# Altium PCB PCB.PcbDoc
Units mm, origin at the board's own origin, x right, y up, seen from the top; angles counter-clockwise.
Board outline 66 x 71.8 mm, 4 copper layers (TOP, GND, PWR, BOTTOM), stack 1.586 mm thick; 30 components, 60 nets, 199 pads, 109 vias.
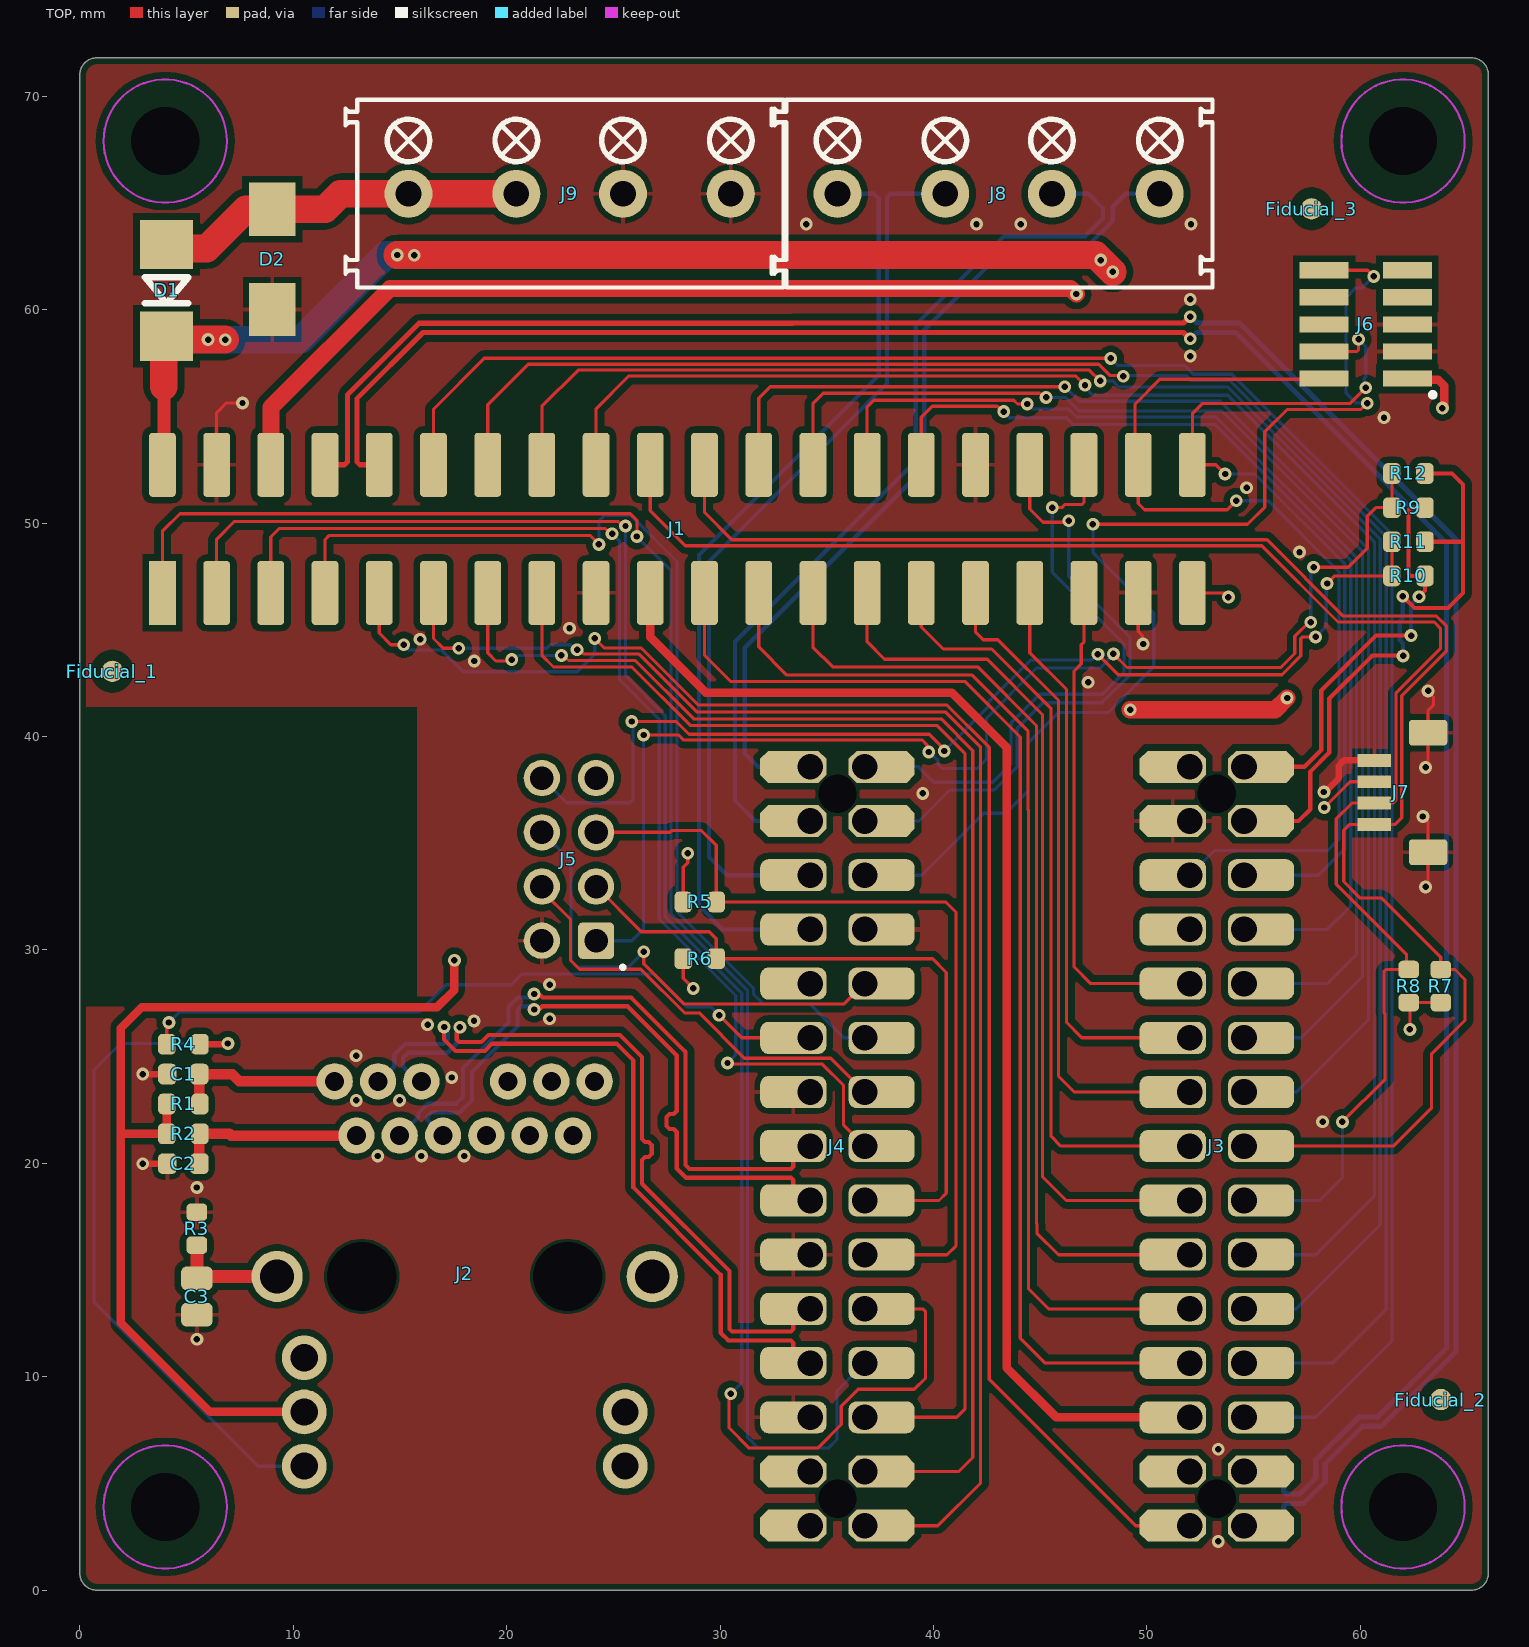
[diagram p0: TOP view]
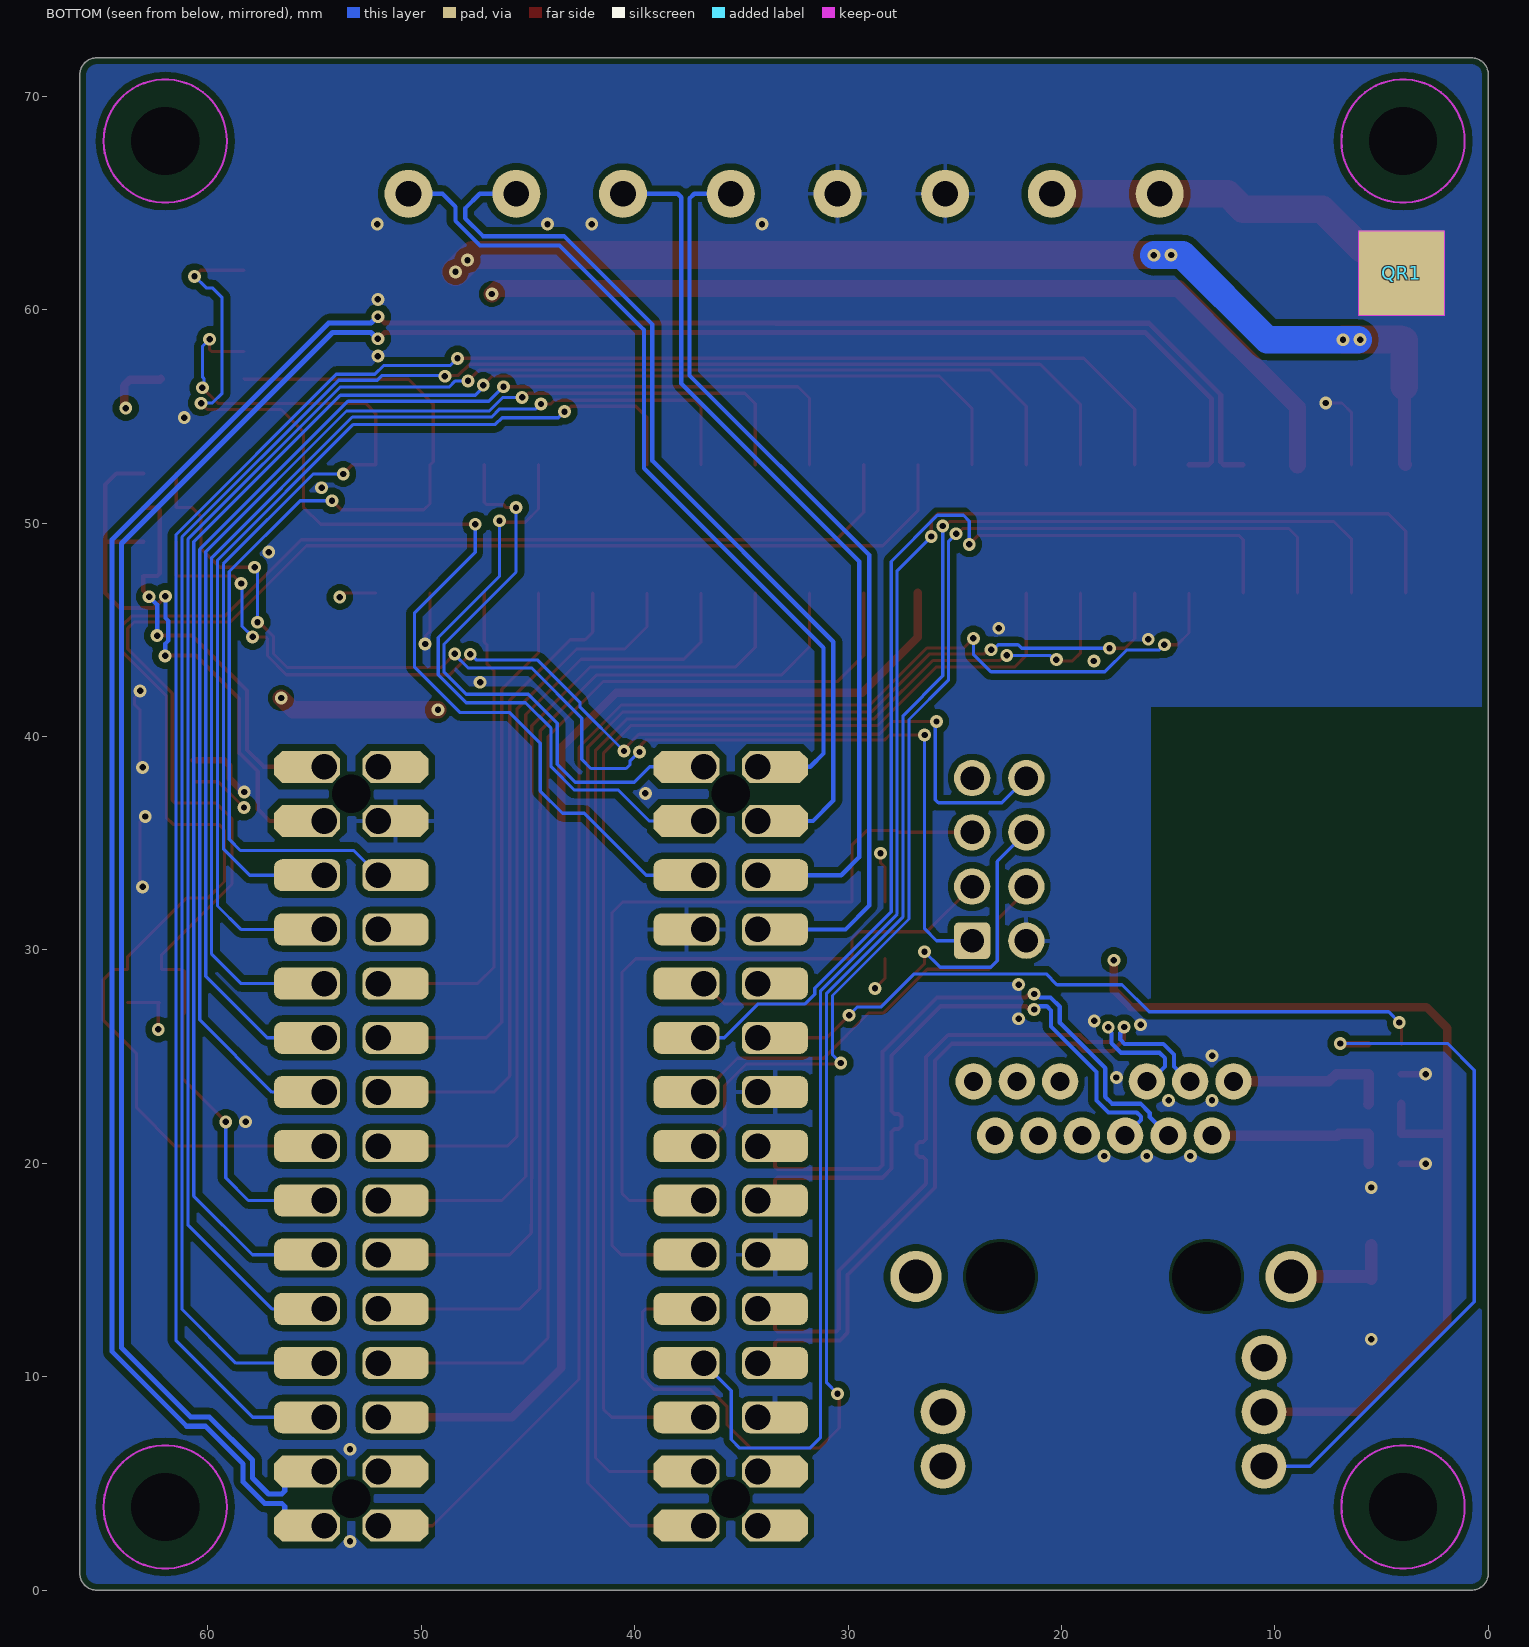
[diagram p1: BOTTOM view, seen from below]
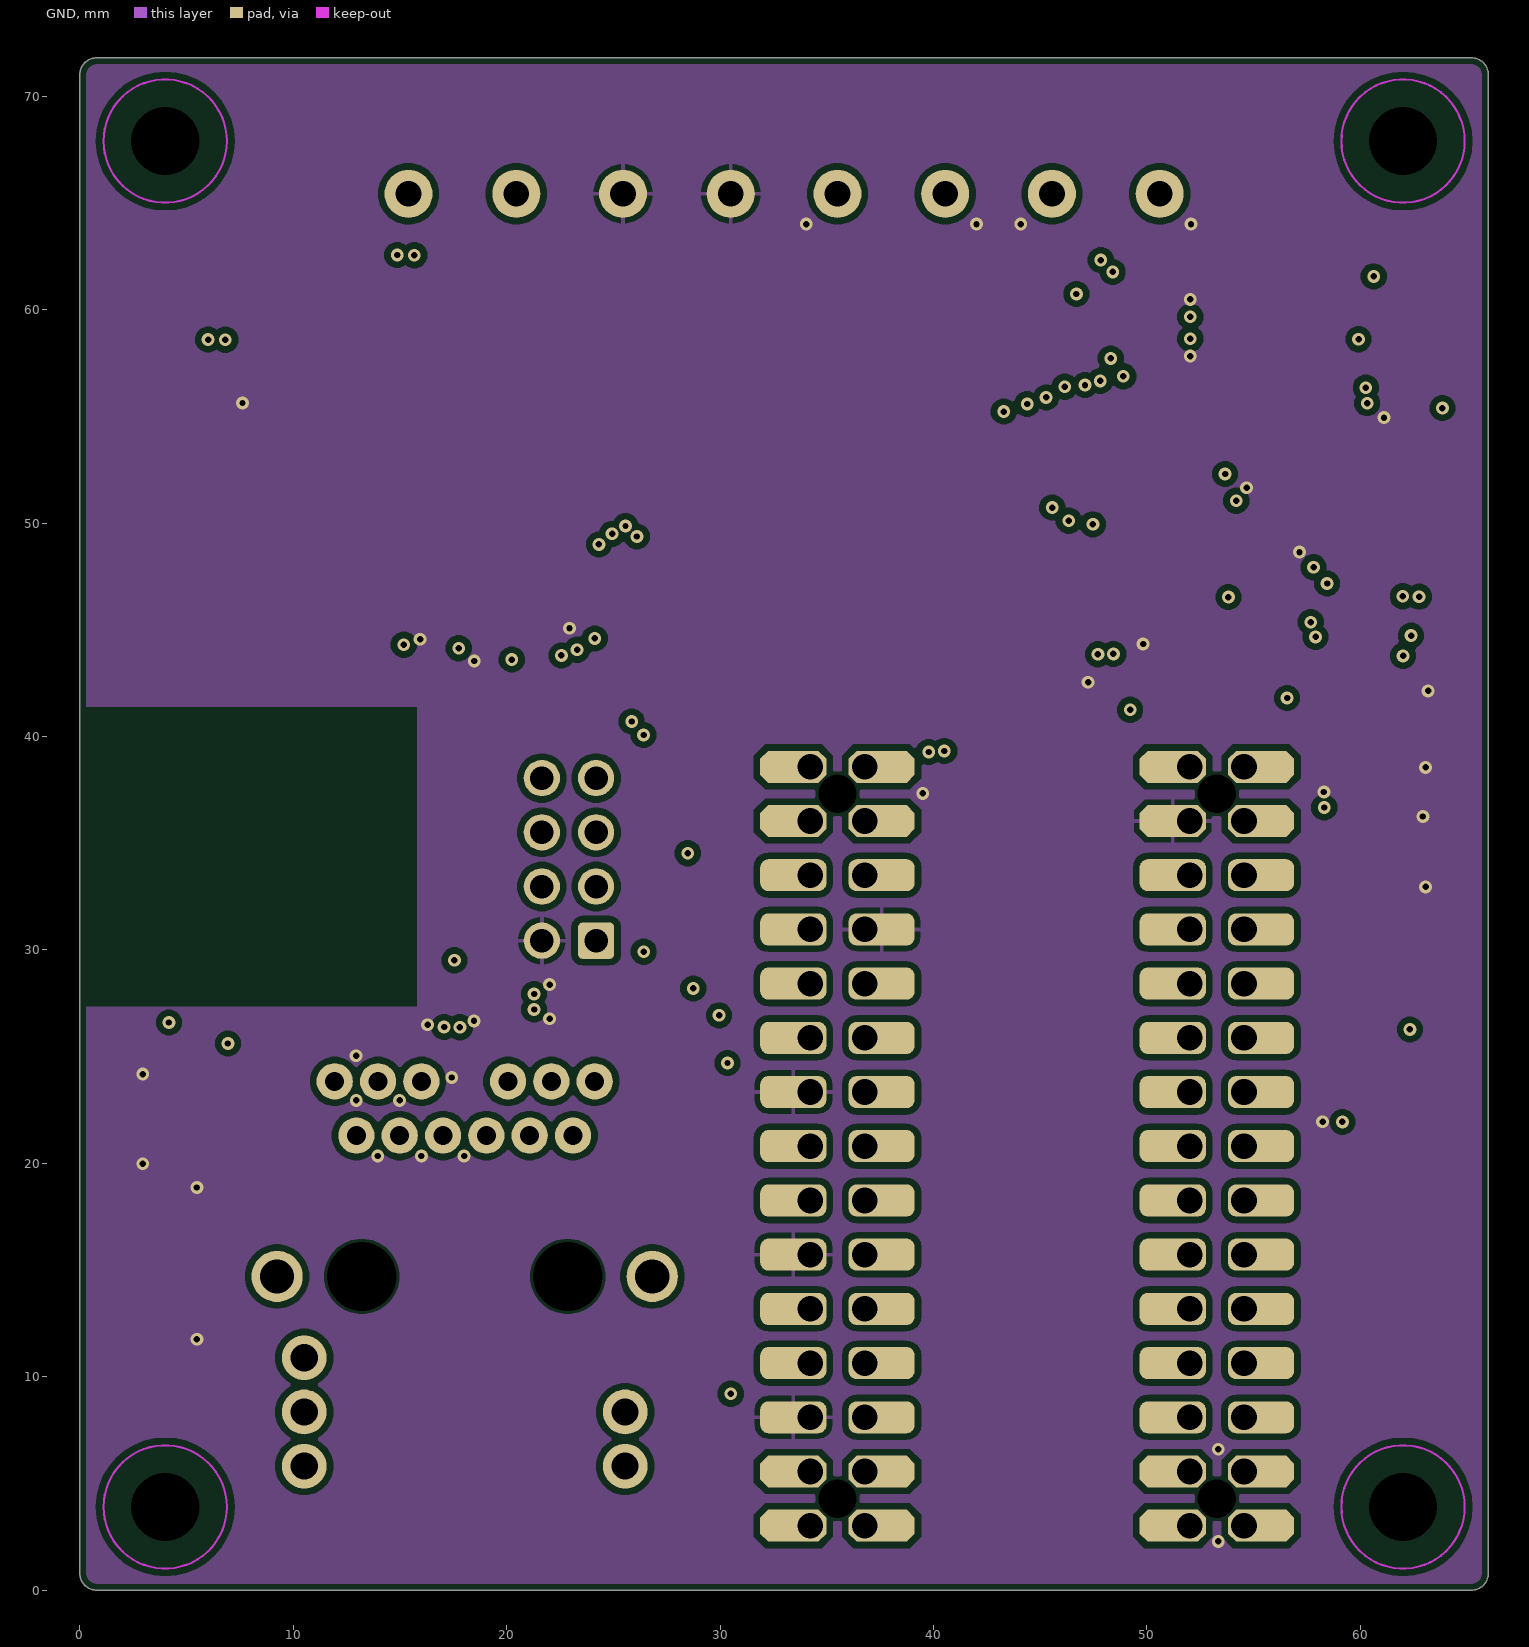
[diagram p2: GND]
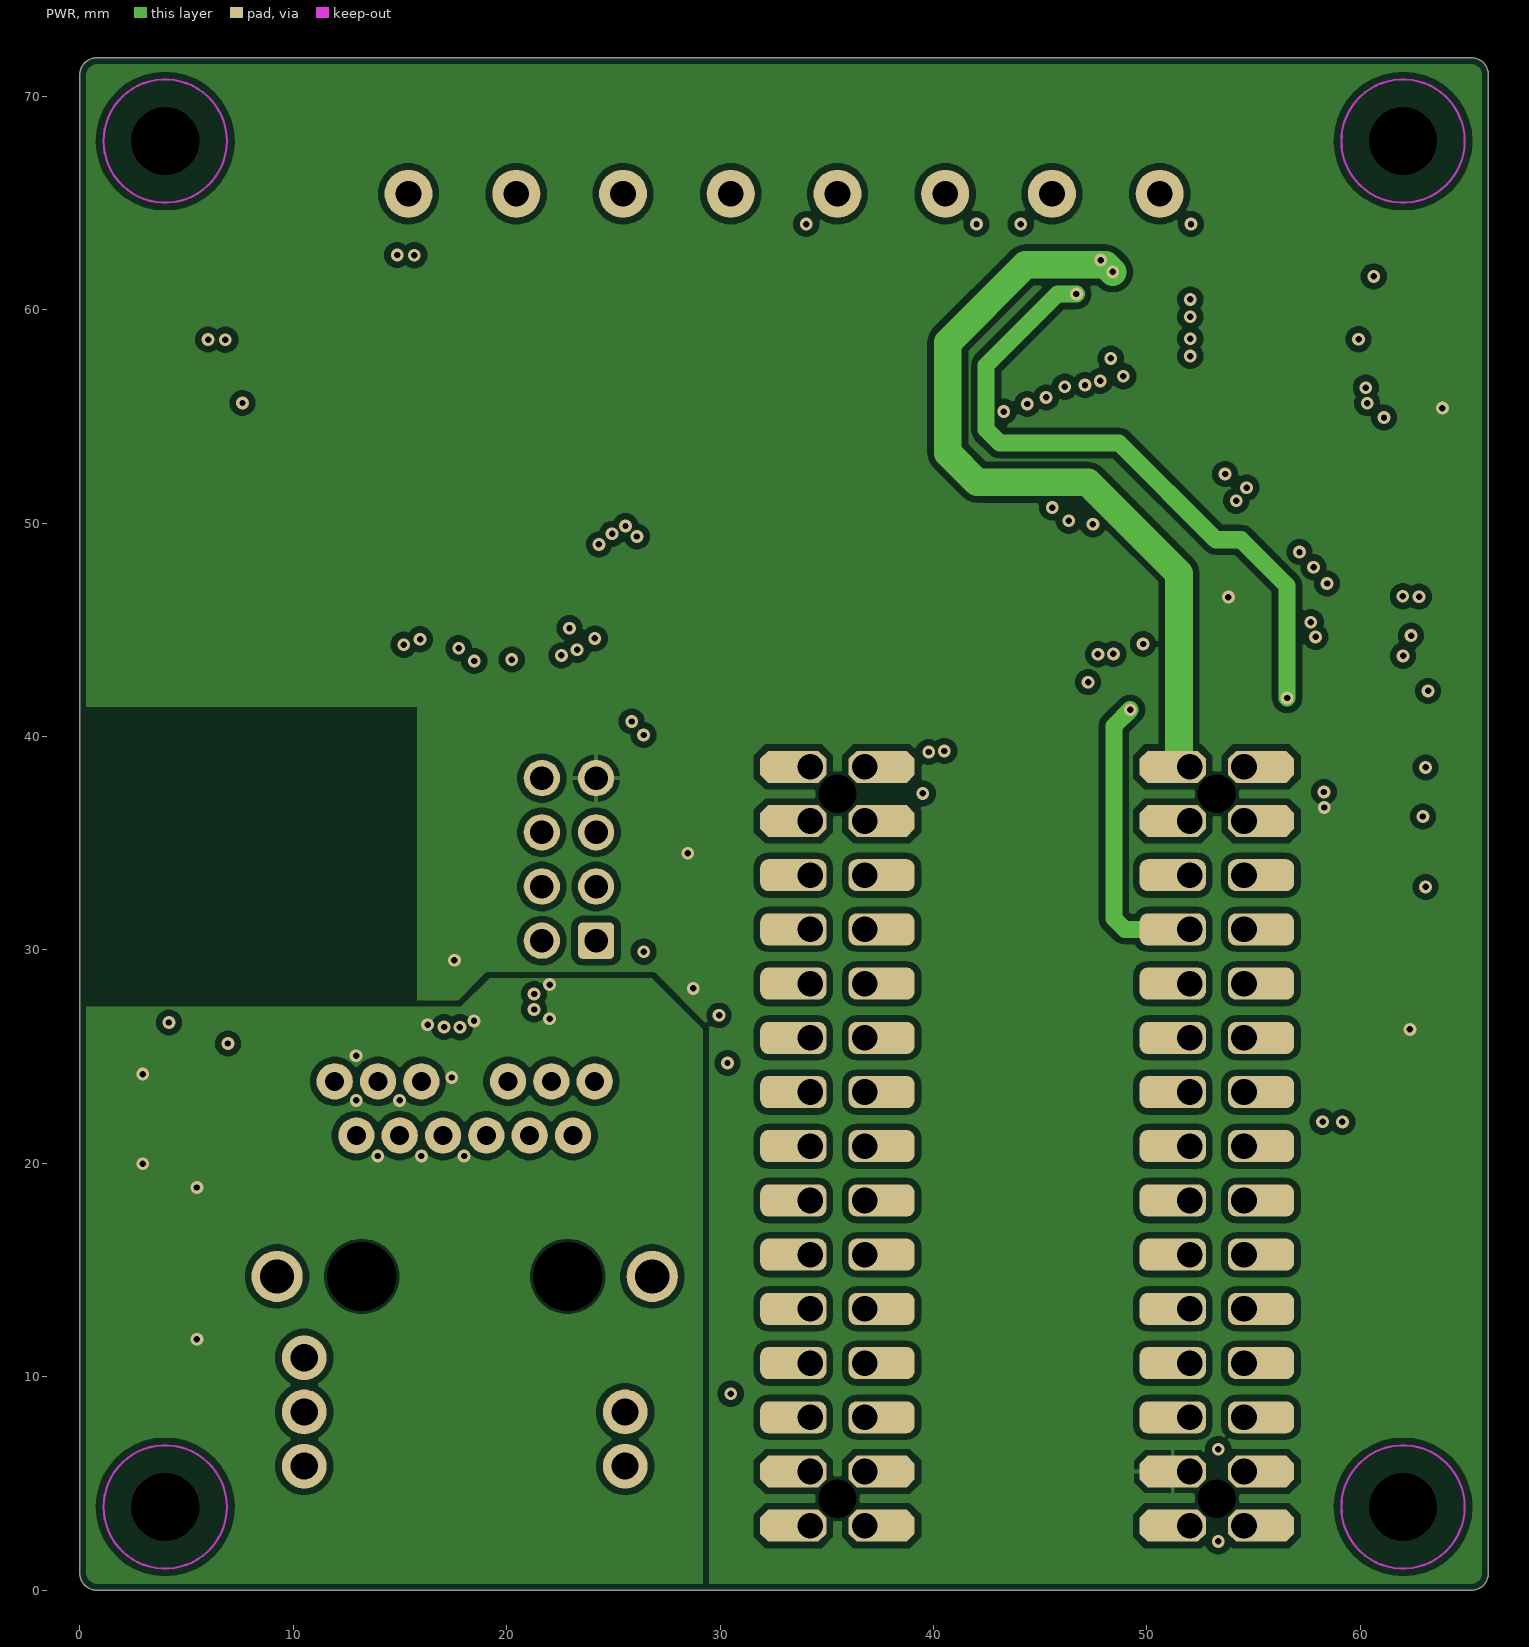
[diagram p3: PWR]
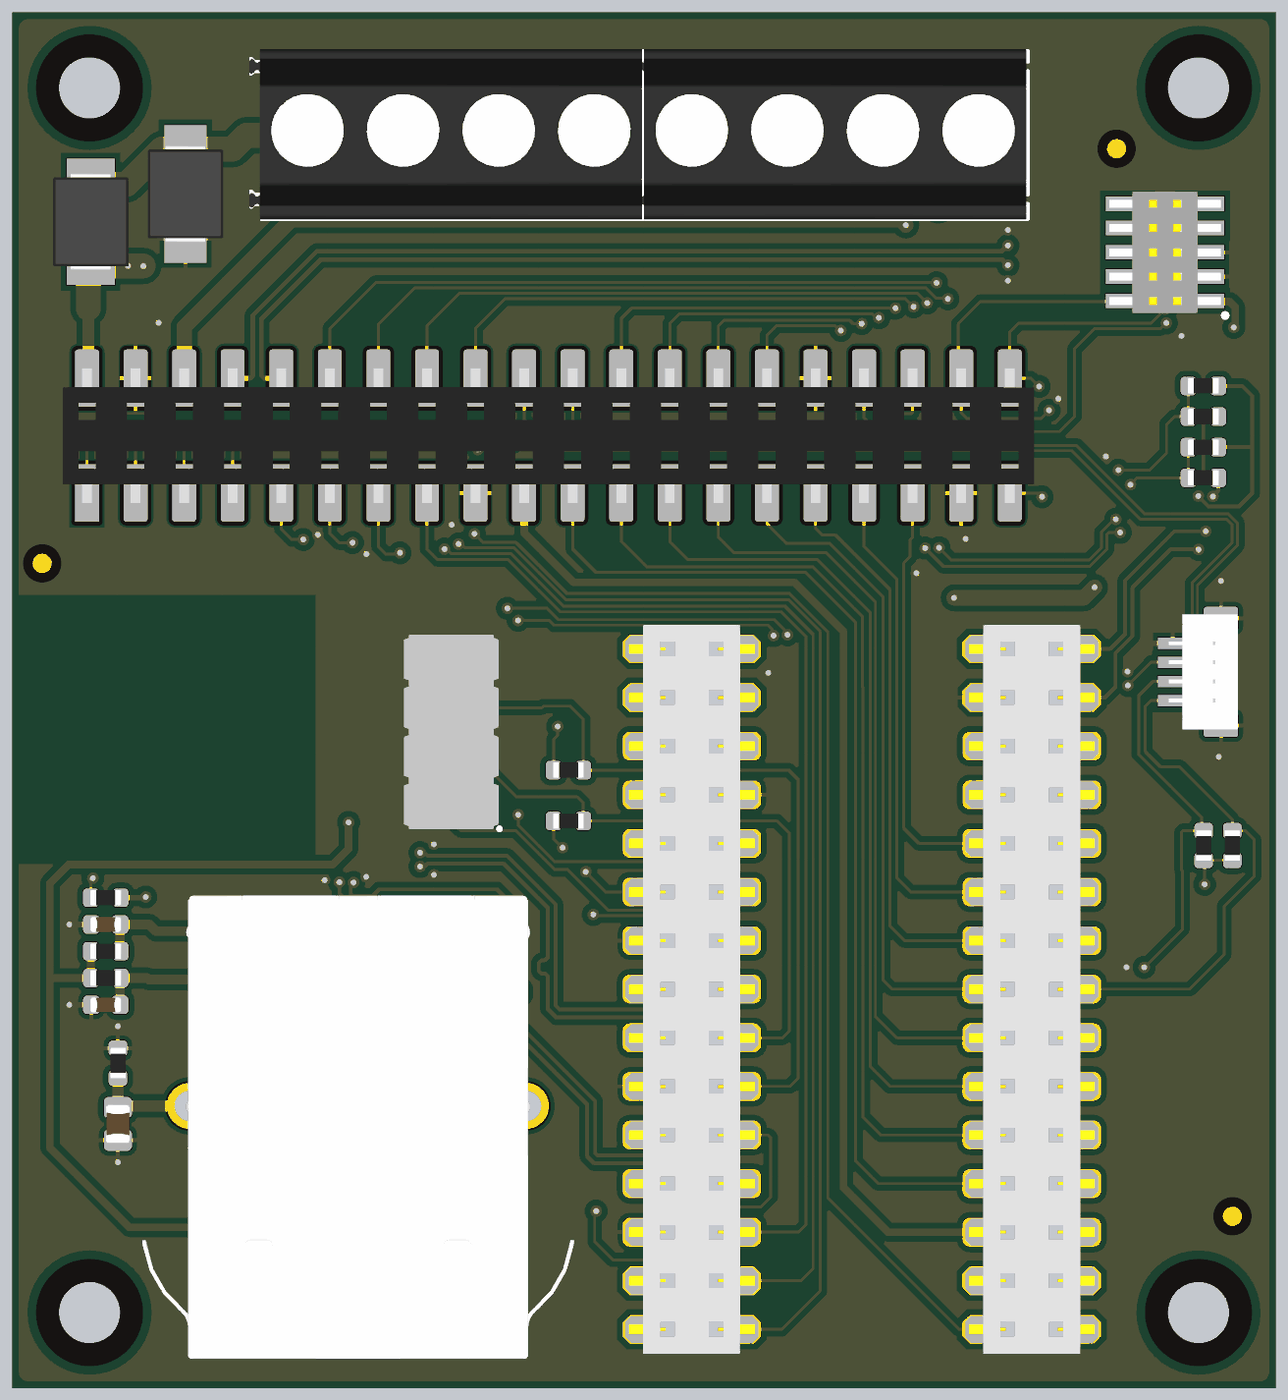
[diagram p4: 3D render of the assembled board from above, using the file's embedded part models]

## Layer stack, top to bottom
Top Solder: solder mask 0.0102, Solder Resist, Dk 3.5
TOP: signal copper 0.018
Dielectric 1: prepreg 0.14, PP-014, Dk 4.2
GND: signal copper 0.035
Dielectric2: core 1.2, FR-4, Dk 4.8
PWR: signal copper 0.035
Dielectric3: prepreg 0.14, PP-014, Dk 4.2
BOTTOM: signal copper 0.018
Bottom Solder: solder mask 0.0102, Solder Resist, Dk 3.5

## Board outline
0.792,0 cw(c0.792,0.792) 0,0.792 0,71.008 cw(c0.792,71.008) 0.792,71.8 65.208,71.8 cw(c65.208,71.008) 66,71.008 66,0.792 cw(c65.208,0.792) 65.208,0

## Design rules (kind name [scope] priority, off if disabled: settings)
BoardOutlineClearance Mousebites [(ObjectKind = 'Pad') And (Name = 'Free-MOUSEBITE')] p1: gap=0 ignorepadtopadclearanceinfootprint=FALSE
BoardOutlineClearance Silks [(OnLayer('Top Overlay') OR OnLayer('Bottom Overlay'))] p2: gap=0 ignorepadtopadclearanceinfootprint=FALSE
BoardOutlineClearance [All] p3: gap=0.3 ignorepadtopadclearanceinfootprint=FALSE
Clearance padNANO [(ObjectKind = 'Pad') And (Net = 'No Net') And (AsMM(HoleDiameter) = 1.8) vs (ObjectKind = 'Pad') And (AsMM(HoleDiameter) = 1.2) And (AsMM(PadXSize_AllLayers) = 1.5) And (AsMM(PadYSize_AllLayers) = 3.1)] p1: gap=0.05 ignorepadtopadclearanceinfootprint=FALSE
Clearance COPPER_0.3mm [All] p2: gap=0.127 ignorepadtopadclearanceinfootprint=FALSE except(0.3: Arc-Fill Arc-Poly Arc-Region Track-Fill Track-Poly Track-Region SMDPad-Fill SMDPad-Poly SMDPad-Region THPad-Fill THPad-Poly THPad-Region Via-Fill Via-Poly Via-Region Fill-Fill Fill-Poly Fill-Region Poly-Poly Poly-Region Region-Region)
Clearance "Generic clearance 0.15mm" [All] p3: gap=0.127 ignorepadtopadclearanceinfootprint=FALSE
ComponentClearance [All] p1: gap=0.2 collisioncheckmode=3 verticalgap=0 showdistances=TRUE
DiffPairsRouting USB [InDifferentialPairClass('USBC_FS')] p1: maxlimit=0.5 minlimit=0.2 mostfreqgap=0.5 toplayer_maxgap=0.2 toplayer_prefgap=0.2 toplayer_minwidth=0.24 toplayer_maxwidth=0.24 toplayer_prefwidth=0.24 midlayer1_mingap=0.5 midlayer1_minwidth=0.162 midlayer1_maxwidth=0.162 midlayer1_prefwidth=0.162 midlayer2_mingap=0.5 midlayer2_minwidth=0.162 midlayer2_maxwidth=0.162 midlayer2_prefwidth=0.162 bottomlayer_maxgap=0.2 bottomlayer_prefgap=0.2 bottomlayer_minwidth=0.24 bottomlayer_maxwidth=0.24 bottomlayer_prefwidth=0.24 impedanceprofiledriven=TRUE impedanceprofileid={3D0335B6-4988-4FA4-A284-C2E821038D5B} impedanceprofilevalue=90.000000 maxuncoupledlength=12.7
DiffPairsRouting ETH [InDifferentialPairClass('ETH')] p2: maxlimit=0.22 minlimit=0.2 mostfreqgap=0.22 toplayer_mingap=0.22 toplayer_minwidth=0.195 toplayer_maxwidth=0.195 toplayer_prefwidth=0.195 midlayer1_maxgap=0.2 midlayer1_prefgap=0.2 midlayer1_minwidth=0.075 midlayer1_maxwidth=0.075 midlayer1_prefwidth=0.075 midlayer2_maxgap=0.2 midlayer2_prefgap=0.2 midlayer2_minwidth=0.075 midlayer2_maxwidth=0.075 midlayer2_prefwidth=0.075 bottomlayer_mingap=0.22 bottomlayer_minwidth=0.195 bottomlayer_maxwidth=0.195 bottomlayer_prefwidth=0.195 impedanceprofiledriven=TRUE impedanceprofileid={F6042609-3D57-4987-B3B1-E88D19C2B591} impedanceprofilevalue=100.000000 maxuncoupledlength=12.7
Height [All] p1: minheight=0 maxheight=30 prefheight=12.7
HoleSize [All] p1: absolutevalues=TRUE maxlimit=30 minlimit=0.3 maxpercent=80.000 minpercent=20.000
HoleToHoleClearance [All] p1: gap=0.25 allowstackedmicrovias=FALSE
MatchedLengths ETH_intra [InDifferentialPairClass('ETH')] p1: tolerance=0.25 checknetsindiffpair=TRUE checkdiffpairvsdiffpair=FALSE checkxsignals=FALSE checkothers=FALSE
MatchedLengths ETH_group [InDifferentialPairClass('ETH')] p2: tolerance=5 checknetsindiffpair=FALSE checkdiffpairvsdiffpair=TRUE checkxsignals=TRUE checkothers=TRUE phasematching=TRUE phasetolerance=0.254 phasedistance=12.7
PlaneConnect [All] p1: pad.planeconnectstyle=Relief pad.reliefexpansion=0.508 pad.reliefentries=4 pad.reliefconductorwidth=0.254 pad.reliefairgap=0.254 via.planeconnectstyle=Direct via.reliefexpansion=0.508 via.reliefentries=4 via.reliefconductorwidth=0.254 via.reliefairgap=0.254
PolygonConnect QR [HasFootprint('QR CODE 4x4mm') vs InNet('GND')] p1: connectstyle=Direct reliefconductorwidth=0.254 reliefentries=4 polygonreliefangle="90 Angle" airgapwidth=0.254
PolygonConnect [All] p2: thpad.connectstyle=Relief thpad.reliefconductorwidth=0.2 thpad.reliefentries=4 thpad.polygonreliefangle="90 Angle" thpad.airgapwidth=0.254 smdpad.connectstyle=Relief smdpad.reliefconductorwidth=0.2 smdpad.reliefentries=4 smdpad.polygonreliefangle="90 Angle" smdpad.airgapwidth=0.254 via.connectstyle=Direct via.reliefconductorwidth=0.254 via.reliefentries=4 via.polygonreliefangle="90 Angle" via.airgapwidth=0.254
RoomDefinition TOP [InComponentClass('TOP')] p1: confinementstyle=ConfineIn formatcopy=TRUE lockcomponents=FALSE outline -25.4,-95.292 25.4,-95.292 25.4,-69.892 -25.4,-69.892
RoutingVias StandardVias [All] p1: holewidth=0.3 width=0.6 viastyle="Through Hole" minholewidth=0.3 minwidth=0.6 maxholewidth=0.3 maxwidth=0.6
SMDToCorner [All] p1: distance=39370
SilkToSilkClearance [All] p1: silktosilkclearance=0.2
SilkToSolderMaskClearance [IsPad] p1: minsilkscreentomaskgap=0.15 clearancetoexposedcopper=TRUE
SolderMaskExpansion VIAtented [IsVia] p1: expansion=0.102 istentingtop=TRUE
SolderMaskExpansion [All] p2: expansion=0.05 istentingtop=FALSE
SupplyNets "Schematic Supply Nets_1" [InNet('VEXT')] p1: voltage=0.000
SupplyNets "Schematic Supply Nets_4" [InNet('+3V3')] p2: voltage=0.000
SupplyNets "Schematic Supply Nets_3" [InNet('+VBUS')] p3: voltage=0.000
SupplyNets "Schematic Supply Nets_2" [InNet('VIN')] p4: voltage=0.000
SupplyNets "Schematic Supply Nets" [InNet('GND')] p5: voltage=0.000
UnConnectedPin [All] p1:
UnRoutedNet [All] p1: checkbadconnections=TRUE
ViasUnderSMD [All] p1: allowed=FALSE
Width StandardTraces [All] p1: maxlimit=5 minlimit=0.127 preferedwidth=0.15
21 further rules are at their usual default settings.

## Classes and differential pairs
differential pair class USBC_FS: USBFS_D_1
differential pair class ETH: ETH_RX_1 ETH_TX_1
differential pair USBFS_D_1: +USBFS_D_1_P -USBFS_D_1_N
differential pair ETH_TX_1: +ETH_TX_1_P -ETH_TX_1_N
differential pair ETH_RX_1: +ETH_RX_1_P -ETH_RX_1_N

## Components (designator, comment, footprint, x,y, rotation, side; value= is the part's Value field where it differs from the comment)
C1 "0603B104K500CT" CAP-0603 4.849,24.181 r0 top value=100nF
C2 "0603B104K500CT" CAP-0603 4.849,19.981 r0 top value=100nF
C3 "FV21X472K102ECG" CAP-0805 5.484,13.758 r90 top value=4.7nF
D1 "S2M_R1_00001" SMB 4.064,60.906 r90 top
D2 "SMBJ24CA" SMB_NOPOLARITY 9.017,62.357 r90 top
Fiducial_1 "Fiducial mark 1mm with 2mm solder" "Fiducial mark 1mm with circle-Footprint-1" 1.524,43.053 r90 top
Fiducial_2 "Fiducial mark 1mm with 2mm solder" "Fiducial mark 1mm with circle-Footprint-1" 63.777,8.932 r90 top
Fiducial_3 "Fiducial mark 1mm with 2mm solder" "Fiducial mark 1mm with circle-Footprint-1" 57.718,64.724 r90 top
J1 "SSM-120-L-DV-P-TR" SSM-120-L-DV-P-TR 28,49.73 r0 top
J2 "TRJT9010A98NL" TRJT9010A98NL 18.034,14.825 r180 top locked
J3 "22TW-159 holes TOP BOTTOM" "HLE-115-02-F-DV holes TOP BOTTOM" 53.28,20.8 r90 top locked
J4 "22TW-159 holes TOP BOTTOM" "HLE-115-02-F-DV holes TOP BOTTOM" 35.5,20.8 r90 top locked
J5 "HC-PM254-5.0H-2x4PZ-02A" "HEADER FEMALE 2.54mm TH 2x4 5mm height" 22.92,34.24 r90 top
J6 "22TW-428" FTSH-105-01-F-DV-Footprint-1 60.253,59.309 r90 top
J7 "BM04B-SRSS-TBT(LF)(SN)(P)" BM04B-SRSS-TB 62.253,37.38 r270 top
J8 "MVE254-5-V-MOxxxx-BK" MVE254-5-V-MOxxxx-BK 43.05,65.43 r0 top
J9 "MVE254-5-V-MOxxxx-BK" MVE254-5-V-MOxxxx-BK 22.95,65.43 r0 top
QR1 "QR CODE 4x4mm" "QR CODE 4x4mm" 4.064,61.706 r180 bottom
R1 "CRCW06030000Z0EAC" RES-0603 4.849,22.781 r180 top value=0
R2 "CRCW06030000Z0EAC" RES-0603 4.849,21.381 r180 top value=0
R3 "RC0603FR-072ML" RES-0603 5.484,16.936 r270 top value=2M
R4 "CRCW0603330RFKEAC" RES-0603 4.849,25.581 r0 top value=330
R5 "CR0603AFX-5101EAS" RES-0603 29.048,32.246 r180 top value=5.1k
R6 "CR0603AFX-5101EAS" RES-0603 29.048,29.591 r180 top value=5.1k
R7 "CR0603AFX-5101EAS" RES-0603 63.771,28.306 r270 top value=5.1k
R8 "CR0603AFX-5101EAS" RES-0603 62.268,28.309 r270 top value=5.1k
R9 "CRCW06030000Z0EAC" RES-0603 62.253,50.724 r180 top value=0
R10 "CRCW06030000Z0EAC" RES-0603 62.253,47.524 r180 top value=0
R11 "CRCW06030000Z0EAC" RES-0603 62.253,49.124 r180 top value=0
R12 "CRCW06030000Z0EAC" RES-0603 62.253,52.324 r180 top value=0

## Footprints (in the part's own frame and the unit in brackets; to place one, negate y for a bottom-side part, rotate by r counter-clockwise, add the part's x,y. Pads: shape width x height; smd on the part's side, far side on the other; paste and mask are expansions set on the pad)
BM04B-SRSS-TB [mm]
  rect 0.6x1.55 smd mask+0.05: 1(-1.5,-1.6) 2(-0.5,-1.6) 3(0.5,-1.6) 4(1.5,-1.6)
  rrect25% 1.2x1.8 smd mask+0.05: FIX(-2.8,0.922) FIX(2.8,0.922)
  body extent -3,-1.8 3,1.8, height 4.33
CAP-0603 [mm] "Chip Capacitor, Body 0603 imperial,1.6x0.8mm, IPC High Density"
  rrect51% 0.87x0.97 smd mask+0.05: 1(-0.75,0) 2(0.75,0)
  body extent -0.8,-0.4 0.8,0.4, height 0.8
CAP-0805 [mm] "Chip Capacitor, Body 0805 imperial, 2.0x1.2mm, IPC Medium Density"
  rrect45% 1.11x1.47 smd mask+0.05: 1(-0.85,0) 2(0.85,0)
  body extent -1,-0.62 1,0.63, height 1.25
"Fiducial mark 1mm with circle-Footprint-1" [mm]
  round 1 smd paste-10 mask+0.5: 1(0,0)
  TOP pour cut-out: 0,1 0.383,0.924 0.707,0.707 0.924,0.383 1,0 1,0 0.924,-0.383 0.707,-0.707 0.383,-0.924 0,-1 0,-1 -0.383,-0.924 -0.707,-0.707 -0.924,-0.383 -1,0 -1,0 -0.924,0.383 -0.707,0.707 -0.383,0.924 0,1
FTSH-105-01-F-DV-Footprint-1 [mm]
  rect 0.76x2.3 smd: 1(-2.54,-1.95) 2(-2.54,1.95) 3(-1.27,-1.95) 4(-1.27,1.95) 5(0,-1.95) 6(0,1.95) 7(1.27,-1.95) 8(1.27,1.95) 9(2.54,-1.95) 10(2.54,1.95)
  silkscreen extent -3.35,-3.19 -3.25,-3.09, body extent -3.17,-2.92 3.17,2.92, height 5.98
"HEADER FEMALE 2.54mm TH 2x4 5mm height" [mm]
  rrect25% 1.7x1.7 hole 1.1 mask+0.1: 1(-3.81,-1.27)
  round 1.7 hole 1.1 mask+0.1: 2(-3.81,1.27) 3(-1.27,-1.27) 4(-1.27,1.27) 5(1.27,-1.27) 6(1.27,1.27) 7(3.81,-1.27) 8(3.81,1.27)
  silkscreen extent -5.11,-2.57 -5.01,-2.47, body extent -5.08,-2.48 5.08,2.48, height 4.57
"HLE-115-02-F-DV holes TOP BOTTOM" [mm]
  oval 1.5x0 hole 1.8 unplated paste-2539.97: 0(-16.51,0) 0(16.51,0)
  oct 1.5x3.1 hole 1.2 copper offset 0,-0.8 mask+0.02: 1(-17.78,-1.27) 2(-15.24,-1.27) 14(15.24,-1.27) 15(17.78,-1.27)
  rrect50% 1.5x3.1 hole 1.2 copper offset 0,-0.8 mask+0.02: 3(-12.7,-1.27) 4(-10.16,-1.27) 5(-7.62,-1.27) 6(-5.08,-1.27) 7(-2.54,-1.27) 8(0.006,-1.27) 9(2.54,-1.27) 10(5.08,-1.27) 11(7.62,-1.27) 12(10.16,-1.27) 13(12.7,-1.27)
  oct 1.5x3.1 hole 1.2 copper offset 0,0.8 mask+0.02: 16(17.78,1.27) 17(15.24,1.27) 29(-15.24,1.27) 30(-17.78,1.27)
  rrect50% 1.5x3.1 hole 1.2 copper offset 0,0.8 mask+0.02: 18(12.7,1.27) 19(10.16,1.27) 20(7.62,1.27) 21(5.08,1.27) 22(2.54,1.27) 23(0.006,1.27) 24(-2.54,1.27) 25(-5.08,1.27) 26(-7.62,1.27) 27(-10.16,1.27) 28(-12.7,1.27)
  body extent -19.05,-3.29 19.05,3.29, height 3.71
MVE254-5-V-MOxxxx-BK [mm]
  round 2.25 hole 1.2 mask+0.05: 1(-7.55,0) 2(-2.5,0) 3(2.5,0) 4(7.55,0)
  silkscreen extent -10.5,-4.39 10.03,4.4, body extent -10.6,-4.4 9.95,4.5, height 16.82
"QR CODE 4x4mm" [mm]
  rect 4x4 smd paste-2539.97 mask+0.1: PAD(0,0)
  TOP keep-out region: -2,2 2,2 2,-2 -2,-2
RES-0603 [mm] "Chip Resistor - Body 0603 imperial,1.6x0.8mm, IPC High Density"
  rrect51% 0.82x0.97 smd mask+0.05: 1(-0.775,0) 2(0.775,0)
  body extent -0.8,-0.4 0.8,0.4, height 0.43
SMB [mm]
  rect 2.3x2.5 smd mask+0.05: A(2.15,0) C(-2.15,0)
  silkscreen extent -0.61,-1.02 0.61,1.02, body extent -2.55,-1.97 2.55,1.97, height 2.65
SMB_NOPOLARITY [mm]
  rect 2.5x2.2 smd: 1(-2.35,0) 2(2.35,0)
  body extent -2.55,-1.97 2.55,1.97, height 2.62
SSM-120-L-DV-P-TR [mm]
  rect 1.25x3 smd mask+0.2: 1(-24.13,-3)
  rrect25% 1.25x3 smd mask+0.2: 2(-24.13,3) 3(-21.59,-3) 4(-21.59,3) 5(-19.05,-3) 6(-19.05,3) 7(-16.51,-3) 8(-16.51,3) 9(-13.97,-3) 10(-13.97,3) 11(-11.43,-3) 12(-11.43,3) 13(-8.89,-3) 14(-8.89,3) 15(-6.35,-3) 16(-6.35,3) 17(-3.81,-3) 18(-3.81,3) 19(-1.27,-3) 20(-1.27,3) 21(1.27,-3) 22(1.27,3) 23(3.81,-3) 24(3.81,3) 25(6.35,-3) 26(6.35,3) 27(8.89,-3) 28(8.89,3) 29(11.43,-3) 30(11.43,3) 31(13.97,-3) 32(13.97,3) 33(16.51,-3) 34(16.51,3) 35(19.05,-3) 36(19.05,3) 37(21.59,-3) 38(21.59,3) 39(24.13,-3) 40(24.13,3)
  body extent -25.4,-3.52 25.4,3.52, height 7.43
TRJT9010A98NL [mm]
  round 1.7 hole 0.89 mask+0.1: 1(-5.075,-6.475) 2(-3.045,-6.475) 3(-1.015,-6.475) 4(1.015,-6.475) 5(3.045,-6.475) 6(5.075,-6.475) 7(-6.09,-9.015) 8(-4.06,-9.015) 9(-2.03,-9.015) 10(2.03,-9.015) 11(4.06,-9.015) 12(6.09,-9.015)
  round 2.1 hole 1.27 mask+0.1: 13(-7.52,6.475) 14(-7.52,9.015) 15(7.52,3.935) 16(7.52,6.475) 17(7.52,9.015)
  round 2 hole 3.25 unplated mask+0.1: NC(-4.825,0.125) NC(4.825,0.125)
  round 2.4 hole 1.6 mask+0.1: SH1(-8.79,0.125) SH2(8.79,0.125)
  body extent -11.31,-10.86 11.29,13.34, height 13.9

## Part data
C1 C2: library part C0043-A.16, "CAP CHIP 0603 100nF 10% 50V X7R", Case Code (Imperial)=0603, Dielectric=X7R, Manufacturer=Walsin, Manufacturer 2=Hottech, Manufacturer 3="Samsung Electro-Mechanics", Part number 2=C1608B104K500NT, Part number 3=CL10B104KB8NNNC, Tolerance=10%, Voltage=50V
C3: library part C0059-A.16, "CAP CHIP 0805 4.7nF 10% 1000V X7R", Case Code (Imperial)=0805, Dielectric=X7R, Manufacturer="PSA Shenzen", Manufacturer 2=KEMET, Part number 2=C0805V472KDRACTU, Part number 3=C0805C472KDRACTU, Tolerance=10%, Voltage=1kV
D1: library part D0003-A.4, "DIODE SMD 1000V 2A SMB", Forward Current=2A, Forward Voltage=1.1V, Manufacturer=Panjit, Max Reverse Voltage (DC)=1kV
D2: library part D0070-A.3, "TVS BIDIRECTIONAL SMD, Reverse standoff 24V, Breakdown min 26.7V, Clamping max 39.8V, 600W, SMB", Manufacturer=Littlefuse, Manufacturer 2=Bourns, Manufacturer 3=Hottech
Fiducial_1 Fiducial_2 Fiducial_3: library part UT0024-A.6
J1: library part J0475-A.2, "PIN HEADER FEMALE SMD 2.54mm VERT. 2x20POS height 7.5mm", LCSC part=C2685092, Manufacturer=Samtech, Manufacturer 2=Liansheng, Part number 2=FH-00148
J2: library part J0561-A.4, "CONN ETH 1x1 RJ45 TH 10/100/1000/2500 integrated magnetics, LED GREEN/YELLOW/ORANGE, micro profile 17.8x24.2x11.55mm", Manufacturer=TRXCOM
J3 J4: library part J0233-A.21, "CONN SMD 2.54mm BOARD FEMALE 30 POS 15X2 holes TOP BOTTOM", Manufacturer=4UCONN, Manufacturer 2=Samtech, Part Number=22TW-159, Part number 2=HLE-115-02-F-DV
J5: library part J0596-A.1, "HEADER 2.54mm TH 2x4POS FEMALE VERTICAL heigth 5mm", LCSC Part #=C42163125, Manufacturer="Hong Cheng"
J6: library part J0089-A.11, "CONN HEADER SMD 10POS 2x5 1.27MM JTAG reel, capsfor pick and place", Color=Black, Current Rating=1.75A, Manufacturer=4UCON, Package Quantity=1
J7: library part J0478-A.4, "CONN JST 4POS VERTICAL 1mm pitch, color neutral, suction tape, tin, QWIIC", LCSC Part #=C160390, Manufacturer=JST
J8 J9: library part J0482-A.1, "CONN SCREW TERMINAL, pitch 5mm, 4POS, 16A, 450V, 2.5mm^2 14AWG, dovetail, BLACK, screw Phillips, housing 20x16.8x8.9mm", Manufacturer=Euroclamp
QR1: library part QR-0001-A.5, "QR CODE 4x4mm on layer 34 (This is not a component)", Manufacturer="This is not a component"
R1 R2 R9 R10 R11 R12: library part R0096-A.23, "RES CHIP 0603 0R 1/10W", Case Code (Imperial)=0603, Manufacturer=Vishay, Power=100mW, Temperature coefficient=0ppm, Tolerance=0%
R3: library part R0428-A.2, "RES CHIP 0603 2M 1% 1/10W", Case Code (Imperial)=0603, Manufacturer=YAGEO, Power=100mW, Temperature coefficient=100ppm, Tolerance=1%
R4: library part R0123-A.23, "RES CHIP 0603 330R 1% 1/10W", Case Code (Imperial)=0603, Manufacturer=Vishay, Power=100mW, Temperature coefficient=100ppm, Tolerance=1%
R5 R6 R7 R8: library part R0239-A.12, "RES CHIP 0603 5k1 1% 1/10W", Case Code (Imperial)=0603, Manufacturer=Bourns, Power=100mW, Temperature coefficient=100ppm, Tolerance=1%

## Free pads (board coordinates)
  round 3 hole 3.2 unplated paste-2539.97 mask+1.3: MH(4,3.9) MH(4,67.9) MH(62,3.9) MH(62,67.9)

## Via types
v1: diameter 0.6, hole 0.3, TOP to BOTTOM, tented both sides, 109 vias

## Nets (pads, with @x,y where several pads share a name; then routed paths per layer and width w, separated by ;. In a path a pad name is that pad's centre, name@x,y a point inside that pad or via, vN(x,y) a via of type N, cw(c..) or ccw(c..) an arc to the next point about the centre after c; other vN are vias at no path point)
+3V3: J1.39 J2.16 J3.29 J5.7 J6.1 J7.2 R1.2 R2.2 R5.2 R6.2 R7.2 R8.2 | length 59.8
  TOP w0.15: R6.2 28.273,28.666 v1(28.743,28.196) ; R5.2 28.273,33.878 28.483,34.088 v1(28.483,34.532) ; J1.39 53.619,46.73 v1(53.819,46.53) ; v1(58.309,36.674) 59.515,37.88 J7.2 ; v1(62.322,26.277) 62.322,27.48 R8.2 62.27,27.531 R7.2
  TOP w0.4: R1.2 R2.2 1.954,21.381 1.928,21.407 ; J2.16 6.1,8.35 1.928,12.522 1.928,21.407 ; v1(17.549,29.515) 17.549,28.118 16.75,27.319 2.907,27.319 1.928,26.34 1.928,21.407 ; J6.1 62.246,56.727 63.643,56.727 63.926,56.444 63.926,55.521 63.847,55.442 v1(63.847,55.388)
+VBUS: J1.6 J3.19 | length 95.3
  TOP w0.8: J1.6 8.95,55.414 14.533,60.997 46.428,60.997 v1(46.693,60.732) ; v1(49.216,41.253) 56.014,41.253 v1(56.566,41.805)
  PWR w0.8: v1(46.693,60.732) 45.81,60.732 42.465,57.387 42.465,54.392 43.105,53.751 48.695,53.751 53.229,49.217 54.414,49.217 56.566,47.065 v1(56.566,41.805) ; v1(49.216,41.253) 48.454,40.491 48.454,31.474 48.968,30.96 J3.19
A0_1: J1.21 J3.27 | length 55.9
  TOP w0.15: J1.21 29.27,43.8 30.489,42.581 41.464,42.581 44.069,39.976 44.069,11.811 45.24,10.64 J3.27
A1_1: J1.23 J3.26 | length 50.9
  TOP w0.15: J1.23 31.81,44.196 33.13,42.876 41.807,42.876 44.422,40.26 44.422,36.593 44.45,36.565 44.45,14.118 45.388,13.18 J3.26
A2_1: J1.25 J3.25 | length 45.9
  TOP w0.15: J1.25 34.35,44.181 35.271,43.26 42.07,43.26 44.826,40.504 44.826,19.268 44.831,19.264 44.831,17.154 44.843,17.142 44.843,16.733 45.857,15.72 J3.25
A3_1: J1.27 J3.24 | length 40.9
  TOP w0.15: J1.27 36.89,44.435 37.706,43.619 42.517,43.619 45.103,41.032 45.103,19.383 46.226,18.26 J3.24
A4_1: J1.29 J3.23 | length 36
  TOP w0.15: J1.29 39.43,45.13 40.462,44.099 42.721,44.099 45.512,41.308 45.512,21.265 45.971,20.806 J3.23
A5_1: J1.31 J3.22 | length 31.1
  TOP w0.15: J1.31 41.97,44.892 42.326,44.536 43.011,44.536 45.859,41.689 45.859,24.088 46.607,23.34 J3.22
A6_1: J1.33 J3.21 | length 26.9
  TOP w0.15: J1.33 44.51,43.927 46.23,42.207 46.23,26.601 46.951,25.88 J3.21
A7_1: J1.35 J3.20 | length 23.5
  TOP w0.15: J1.35 47.05,44.422 46.924,44.295 46.924,43.405 46.589,43.071 46.589,29.201 47.371,28.42 J3.20
AREF_1: J1.19 J3.28 | length 59.5
  TOP w0.4: J1.19 26.73,44.661 29.331,42.06 40.858,42.06 43.434,39.484 43.434,10.414 45.748,8.1 J3.28
CANH_1: J4.19 J8.1 | length 44.3
  BOTTOM w0.2: J4.19 30.127,30.96 29.01,32.077 29.01,48.499 37.429,56.919 37.429,65.214 37.213,65.43 J8.1
CANL_1: J4.18 J8.2 | length 42.3
  BOTTOM w0.2: J4.18 30.326,33.5 29.479,34.347 29.479,48.197 37.822,56.54 37.822,65.266 37.986,65.43 J8.2
ETH_RX_1_N: J2.5 J4.23 | length 30.3
  TOP w0.195: v1(21.287,27.934) 21.365,27.856 21.593,27.856 21.675,27.774 25.835,27.774 28.384,25.226 28.384,19.928 28.571,19.74 33.316,19.74 33.43,19.855 33.43,20.174 34.061,20.806 J4.23
  BOTTOM w0.195: J2.5 15.003,21.3 15.867,22.164 15.867,22.357 16.304,22.795 17.631,22.795 17.953,23.117 17.953,24.459 20.085,26.59 20.085,27.34 20.523,27.778 21.022,27.778 v1@21.178,27.934
ETH_RX_1_P: J2.4 J4.24 | length 30
  TOP w0.195: v1@21.55,27.241 21.668,27.359 25.663,27.359 27.969,25.054 27.969,23.254 27.969,22.454 27.828,22.313 27.634,22.313 27.493,22.173 27.493,21.751 27.634,21.61 27.828,21.61 27.969,21.469 27.969,20.528 27.969,19.756 28.399,19.325 33.316,19.325 33.43,19.211 33.43,18.891 34.061,18.26 J4.24
  BOTTOM w0.195: J2.4 17.005,21.3 16.282,22.024 16.282,22.185 16.476,22.38 17.803,22.38 18.369,22.946 18.369,24.287 20.5,26.418 20.5,27.168 20.695,27.363 21.022,27.363 21.178,27.207 v1(21.287,27.207)
ETH_TX_1_N: J2.10 J4.26 | length 34.6
  TOP w0.195: v1(17.808,26.376) 17.808,26.266 17.662,26.12 17.662,25.797 17.776,25.683 18.812,25.683 19.151,26.021 25.312,26.021 26.349,24.984 26.349,22.538 26.349,21.14 26.49,21 26.655,21 26.795,20.859 26.795,20.437 26.655,20.297 26.49,20.297 26.349,20.156 26.349,19.355 26.349,19.042 30.443,14.948 30.443,12.232 30.557,12.118 33.316,12.118 33.43,12.232 33.43,12.549 34.061,13.18 J4.26
  BOTTOM w0.195: J2.10 15.843,23.84 15.147,24.536 15.147,24.926 15.404,25.183 17.219,25.183 17.662,25.625 17.662,26.12 17.808,26.266 v1(17.808,26.376)
ETH_TX_1_P: J2.11 J4.27 | length 34.7
  TOP w0.195: v1(17.07,26.39) 17.07,25.802 17.604,25.267 18.384,25.267 18.984,25.267 19.322,25.606 25.14,25.606 25.934,24.812 25.934,18.87 30.028,14.776 30.028,12.06 30.385,11.702 33.316,11.702 33.43,11.588 33.43,11.271 34.061,10.64 J4.27
  BOTTOM w0.195: J2.11 14.135,23.84 14.135,23.939 14.732,24.536 14.732,25.098 15.232,25.598 17.047,25.598 17.246,25.797 17.246,26.103 17.07,26.28 v1(17.07,26.39)
GND: C1.1 C2.1 C3.1 D2.1 J1.4 J1.17 J1.32 J1.37 J3.17 J4.12 J4.22 J4.25 J4.28 J5.2 J6.3 J6.5 J7.1 J7.FIX J9.3 J9.4 QR1.PAD R3.1 | length 19.3
  TOP w0.15: J1.4 6.41,55.178 6.858,55.626 v1(7.62,55.626) ; J1.37 49.59,44.932 49.79,44.732 49.79,44.363 v1(49.821,44.332) ; v1(62.932,36.253) 63.175,36.009 63.175,34.58 63.175,33.067 v1(63.059,32.951) ; v1(63.059,38.551) 63.175,38.667 63.175,40.18 63.175,41.236 63.433,41.494 63.433,41.829 63.177,42.085 v1(63.177,42.138)
  TOP w0.3: v1(2.944,19.981) C2.1 ; v1(2.944,24.181) C1.1 ; v1(58.292,37.4) 58.355,37.4 58.986,38.031 58.986,38.631 59.235,38.88 J7.1
  other v1: 53.34,2.286 53.34,6.604 5.484,11.753 5.484,18.866 13.961,20.345 16.005,20.345 18.008,20.345 58.233,21.949 12.952,22.947 14.982,22.947 17.429,24.021 12.946,25.041 16.297,26.494 18.471,26.674 22.011,26.772 22.011,28.373 39.5,37.333 47.244,42.545 18.482,43.539 15.942,44.555 22.942,45.073 57.15,48.641 54.67,51.659 61.11,54.941 52.032,57.824 52.032,60.479 34.036,64.008 42.014,64.008 44.086,64.008 52.064,64.008
I2C3_SCL_1: J1.22 J3.8 J7.4 R7.1 | length 78.5
  TOP w0.15: J1.22 29.27,50.502 30.555,49.217 55.632,49.217 59.207,45.642 63.569,45.642 64.03,45.18 64.03,43.992 61.944,41.906 61.944,36.194 61.63,35.88 J7.4 59.5,35.88 59.22,35.6 59.22,33.208 59.998,32.429 61.005,32.429 63.771,29.663 R7.1 64.433,29.081 64.906,28.609 64.906,26.702 63.338,25.134 63.338,22.595 61.548,20.806 J3.8
I2C3_SDA_1: J1.20 J3.7 J7.3 R8.1 | length 78.6
  TOP w0.15: J1.20 26.73,50.585 28.374,48.94 55.377,48.94 58.953,45.365 63.454,45.365 63.753,45.066 63.753,44.107 61.667,42.02 61.667,37.019 61.528,36.88 J7.3 59.611,36.88 58.868,36.138 58.868,33.083 62.168,29.783 62.168,29.084 61.2,29.084 61.112,28.996 61.112,27.04 61.162,26.989 61.162,23.942 v1(59.161,21.941)
  BOTTOM w0.15: J3.7 58.1,18.26 59.161,19.32 v1(59.161,21.941)
LED_ACT_1: J4.21 R4.1 | length 33.3
  TOP w0.15: R4.1 4.074,26.5 v1(4.173,26.599) ; v1(29.955,26.936) 31.011,25.88 J4.21
  BOTTOM w0.15: v1(4.173,26.599) 4.675,27.101 15.897,27.101 17.168,28.372 20.216,28.372 20.719,28.875 26.897,28.875 28.443,27.329 29.562,27.329 v1(29.955,26.936)
NetC1_2: C1.2 J2.12 R1.1 | length 7.9
  TOP w0.5: R1.1 5.599,22.806 C1.2 7.135,24.181 7.477,23.84 J2.12
NetC2_2: C2.2 J2.6 R2.1 | length 8.8
  TOP w0.5: C2.2 5.599,21.356 R2.1 7.014,21.381 7.096,21.3 J2.6
NetC3_2: C3.2 J2.SH2 R3.2 | length 5.4
  TOP w0.6: R3.2 C3.2 5.576,14.7 J2.SH2
NetJ1_24: J1.24 J3.9 | length 64.3
  TOP w0.15: J1.24 31.81,55.851 32.349,56.39 v1(46.15,56.39)
  BOTTOM w0.15: v1(46.15,56.39) 46.831,55.71 53.439,55.71 60.38,48.768 60.38,26.72 57,23.34 J3.9
NetJ1_26: J1.26 J3.10 | length 58.5
  TOP w0.15: J1.26 34.35,55.598 34.837,56.085 44.965,56.085 45.162,55.888 v1(45.278,55.888)
  BOTTOM w0.15: v1(45.278,55.888) 46.173,55.888 46.808,55.253 53.504,55.253 60.103,48.653 60.103,28.761 57.223,25.88 J3.10
NetJ1_28: J1.28 J3.11 | length 53.3
  TOP w0.15: J1.28 36.89,55.446 37.199,55.755 43.759,55.755 43.934,55.58 v1(44.39,55.58)
  BOTTOM w0.15: v1(44.39,55.58) 44.62,55.35 46.319,55.35 46.699,54.97 53.228,54.97 59.826,48.371 59.826,29.802 58.444,28.42 J3.11
NetJ1_30: J1.30 J3.12 | length 47.2
  TOP w0.15: J1.30 39.43,54.962 39.946,55.478 42.982,55.478 43.237,55.223 v1(43.292,55.223)
  BOTTOM w0.15: v1(43.292,55.223) 43.575,54.94 46.216,54.94 46.533,54.623 53.182,54.623 59.549,48.256 59.549,32.058 58.451,30.96 J3.12
NetJ2_17: J2.17 R4.2 | length 32
  TOP w0.3: R4.2 6.904,25.581 v1(6.939,25.617)
  BOTTOM w0.15: v1(6.939,25.617) 1.907,25.617 0.658,24.369 0.658,13.513 8.362,5.81 J2.17
PA20_TCC4_WO0_1: J1.5 J4.8 | length 55.4
  TOP w0.15: J1.5 8.95,49.349 9.349,49.747 24.625,49.747 24.876,49.497 v1(24.94,49.497) ; v1(30.348,24.702) 30.399,24.651 34.784,24.651 35.785,23.649 35.785,21.79 J4.8
  BOTTOM w0.15: v1(24.94,49.497) 25.291,49.145 25.291,42.654 27.15,40.795 27.15,31.448 30.734,27.864 30.734,25.087 v1(30.348,24.702)
PA21_TCC4_WO1_1: J4.9 J5.4 | length 20.3
  TOP w0.15: J5.4 21.65,32.777 22.991,31.437 22.991,29.516 23.413,29.093 26.287,29.093 28.332,27.048 29.021,27.048 31.141,24.928 35.182,24.928 J4.9
PA23_TCC5_WO1_1: J1.3 J4.5 | length 84.4
  TOP w0.15: J1.3 6.41,49.247 7.238,50.074 25.234,50.074 25.447,49.862 v1(25.568,49.862) ; v1(30.5,9.204) 30.42,9.124 30.42,7.598 31.361,6.657 34.571,6.657 35.678,7.764 35.678,8.627 36.467,9.416 39.104,9.416 39.629,9.941 39.629,13.043 39.492,13.18 J4.5
  BOTTOM w0.15: v1(25.568,49.862) 25.568,42.839 27.427,40.981 27.427,31.563 31.011,27.979 31.011,9.715 v1(30.5,9.204)
PB11_TCC3_WO6_1: J4.7 J5.3 R6.1 | length 32.9
  TOP w0.15: J5.3 26.312,30.849 29.495,30.849 29.823,30.521 R6.1 29.827,29.587 39.958,29.587 40.601,28.944 40.601,18.604 40.257,18.26 J4.7
PB24_TCC6_WO1_1: J1.1 J4.4 | length 79.4
  TOP w0.15: J1.1 3.87,49.616 4.693,50.44 25.795,50.44 26.103,50.132 v1(26.103,49.369)
  BOTTOM w0.15: v1(26.103,49.369) 27.704,47.768 27.704,31.678 31.288,28.093 31.288,7.161 31.792,6.657 35.076,6.657 35.478,7.059 35.478,9.348 J4.4
PC19_TCC1_WO4_1: J4.11 J5.6 | length 22.5
  TOP w0.15: v1(26.42,29.915) 26.42,29.352 28.304,27.468 35.818,27.468 J4.11
  BOTTOM w0.15: J5.6 23.014,34.147 23.014,29.485 23.313,29.186 25.69,29.186 v1(26.42,29.915)
PC20_TCC1_WO5_1: J1.7 J4.10 | length 49.2
  TOP w0.15: J1.7 11.49,49.215 11.695,49.42 23.903,49.42 v1(24.324,49)
  BOTTOM w0.15: v1(24.324,49) 24.324,50.094 24.594,50.364 25.818,50.364 27.981,48.201 27.981,31.792 31.565,28.208 31.565,27.919 32.016,27.468 34.208,27.468 35.796,25.88 J4.10
PD11_TCC2_WO2_1: J4.6 J5.5 R5.1 | length 40.1
  TOP w0.15: J5.5 27.646,35.51 27.728,35.592 29.131,35.592 29.823,34.9 R5.1 40.57,32.246 41.06,31.755 41.06,16.146 40.634,15.72 J4.6
R\E\S\E\T\_1: J4.13 J6.10 | length 53.9
  TOP w0.15: v1(47.468,49.942) 54.714,49.942 55.522,50.75 55.522,54.277 56.568,55.322 60.024,55.322 v1(60.319,55.618) ; J6.10 60.338,61.849 v1(60.626,61.561)
  BOTTOM w0.15: J4.13 39.456,33.5 42.356,36.399 43.382,36.399 44.422,37.439 44.422,39.692 45.849,41.119 48.177,41.119 50.323,43.265 50.323,45.774 47.468,48.629 v1(47.468,49.942) ; v1(60.319,55.618) 60.304,55.633 59.784,55.633 59.332,56.084 59.332,60.565 59.787,61.02 60.085,61.02 v1(60.626,61.561)
"RS485 A_1": J4.17 J8.3 | length 43.7
  BOTTOM w0.2: J4.17 31.651,36.04 30.695,36.996 30.695,44.439 39.173,52.918 39.173,59.309 43.31,63.446 47.109,63.446 47.946,64.283 47.946,64.748 47.263,65.43 J8.3
"RS485 B_1": J4.16 J8.4 | length 40.7
  BOTTOM w0.2: J4.16 31.778,38.58 31.157,39.201 31.157,44.159 39.567,52.57 39.567,59.055 43.519,63.006 47.244,63.006 48.4,64.162 48.4,64.82 49.01,65.43 J8.4
RXD_1: J5.8 R10.2 R11.2 | length 52.3
  TOP w0.15: v1(25.858,40.704) 27.948,40.704 28.543,40.109 39.804,40.109 40.503,39.41 v1(40.503,39.322) ; v1(47.704,43.851) 48.659,42.896 56.33,42.896 57.208,43.774 57.208,44.58 57.296,44.667 v1(57.905,44.667) ; v1(58.443,47.168) 58.799,47.524 R10.2 R11.2
  BOTTOM w0.15: J5.8 22.805,36.896 25.769,36.896 25.914,37.04 25.914,40.648 v1(25.858,40.704) ; v1(40.503,39.322) 42.567,41.386 42.567,41.605 44.544,43.582 47.407,43.582 47.677,43.851 v1(47.704,43.851) ; v1(57.905,44.667) 58.4,45.162 58.4,47.124 v1(58.443,47.168)
SPI2_CS_1: J1.18 J3.6 | length 80.9
  TOP w0.15: J1.18 24.19,55.357 25.725,56.892 46.672,56.892 v1(47.1,56.465)
  BOTTOM w0.15: v1(47.1,56.465) 47.1,56.357 47.47,55.987 53.792,55.987 60.657,49.122 60.657,18.467 57.911,15.72 J3.6
SPI2_MISO_1: J1.14 J3.4 | length 93
  TOP w0.15: J1.14 19.11,55.553 21.003,57.446 47.734,57.446 48.26,56.92 48.851,56.92 v1(48.892,56.88)
  BOTTOM w0.15: v1(48.892,56.88) 48.932,56.92 51.834,56.92 52.059,56.695 53.867,56.695 61.211,49.351 61.211,13.164 58.687,10.64 J3.4
SPI2_MOSI_1: J1.12 J3.3 | length 98.1
  TOP w0.15: J1.12 16.57,55.343 18.953,57.725 48.292,57.725 v1(48.303,57.715)
  BOTTOM w0.15: v1(48.303,57.715) 48.636,57.382 51.765,57.382 52.174,56.972 53.982,56.972 61.488,49.466 61.488,11.686 57.903,8.1 J3.3
SPI2_SCLK_1: J1.16 J3.5 | length 86.1
  TOP w0.15: J1.16 21.65,55.47 23.349,57.169 47.302,57.169 v1(47.809,56.661)
  BOTTOM w0.15: v1(47.809,56.661) 48.4,56.661 48.684,56.378 53.793,56.378 60.934,49.236 60.934,17.114 57,13.18 J3.5
SPI5_CS_1: J1.15 J4.3 | length 60.2
  TOP w0.15: J1.15 21.65,43.8 22.194,43.255 25.868,43.255 28.602,40.521 40.158,40.521 41.469,39.21 41.469,8.487 41.082,8.1 J4.3
SPI5_MISO_1: J1.11 J4.1 | length 70.8
  TOP w0.15: J1.11 16.57,44.594 17.027,44.136 v1(17.755,44.136) ; v1(23.3,44.064) 23.42,44.064 23.613,43.871 26.182,43.871 28.9,41.153 40.549,41.153 42.205,39.497 42.205,5.021 40.204,3.02 J4.1
  BOTTOM w0.15: v1(17.755,44.136) 21.874,44.136 22.038,44.301 22.971,44.301 23.207,44.064 v1(23.3,44.064)
SPI5_MOSI_1: J1.13 J4.2 | length 66.1
  TOP w0.15: J1.13 19.11,43.927 19.498,43.539 20.174,43.539 v1(20.239,43.604) ; v1(22.565,43.798) 22.66,43.798 22.896,43.562 26.03,43.562 28.769,40.824 40.359,40.824 41.842,39.341 41.842,6.217 41.185,5.56 J4.2
  BOTTOM w0.15: v1(20.239,43.604) 20.361,43.604 20.555,43.798 v1(22.565,43.798)
SPI5_SCK_1: J1.9 J3.30 | length 76.3
  TOP w0.15: J1.9 14.03,44.848 14.577,44.301 v1(15.18,44.301) ; v1(24.13,44.598) 24.58,44.148 26.308,44.148 28.981,41.475 40.624,41.475 42.612,39.487 42.612,9.884 49.476,3.02 J3.30
  BOTTOM w0.15: v1(15.18,44.301) 15.434,44.047 16.958,44.047 17.974,43.031 23.308,43.031 24.13,43.853 v1(24.13,44.598)
SWCLK_1: J1.40 J3.13 J6.4 | length 43.3
  TOP w0.15: v1(53.661,52.302) 53.232,52.73 J1.40 52.13,55.13 52.609,55.609 59.525,55.609 v1(60.258,56.342) ; J6.4 59.83,58.039 59.918,58.127 v1(59.918,58.615)
  BOTTOM w0.15: v1(53.661,52.302) 55.058,52.302 59.272,48.087 59.272,34.737 58.036,33.5 J3.13 ; v1(59.918,58.615) 60.258,58.275 60.258,56.85 60.187,56.78 60.187,56.413 v1(60.258,56.342)
SWDIO_1: J1.38 J3.18 J6.2 | length 45.4
  TOP w0.15: v1(54.183,51.049) 53.757,50.622 49.885,50.622 49.59,50.918 J1.38 49.44,52.881 49.44,55.575 50.601,56.736 58.27,56.736 J6.2
  BOTTOM w0.15: J3.18 53.168,34.658 58.475,34.658 58.995,35.179 58.995,47.729 55.676,51.049 v1(54.183,51.049)
TXD_1: J5.1 R9.2 R12.2 | length 58.6
  TOP w0.15: v1(26.416,40.071) 28.062,40.071 28.303,39.83 39.484,39.83 39.692,39.622 39.692,39.361 v1(39.778,39.275) ; v1(48.43,43.869) 49.068,43.231 56.274,43.231 56.931,43.889 56.931,44.694 57.594,45.357 v1(57.675,45.357) ; v1(57.808,47.93) 59.435,47.93 60.327,48.821 60.327,50.322 60.729,50.724 R9.2 R12.2
  BOTTOM w0.15: J5.1 25.858,30.43 26.416,30.988 v1(26.416,40.071) ; v1(39.778,39.275) 39.807,39.275 40.217,38.866 40.217,38.687 40.402,38.502 42.052,38.502 42.484,38.935 42.484,40.865 44.827,43.208 47.805,43.208 48.43,43.833 v1(48.43,43.869) ; v1(57.675,45.357) 57.675,47.797 v1(57.808,47.93)
UART1_RX_1: J3.15 R9.1 R10.1 | length 19.7
  TOP w0.2: J3.15 57.376,38.58 58.166,39.37 58.166,42.155 60.739,44.729 v1(62.378,44.729) ; v1(62.753,46.551) 62.753,46.566 63.028,46.841 R10.1 62.37,47.524 62.253,47.641 62.253,50.604 62.374,50.724 R9.1
  BOTTOM w0.2: v1(62.378,44.729) 62.378,46.176 v1(62.753,46.551)
UART1_TX_1: J3.14 R11.1 R12.1 | length 28.3
  TOP w0.2: J3.14 57.107,36.04 57.658,36.591 57.658,38.354 58.547,39.243 58.547,41.783 60.563,43.799 61.983,43.799 v1(62.003,43.779) ; v1(61.99,46.571) v1(61.99,46.571) 62.535,46.024 64.113,46.024 64.812,46.723 64.812,49.124 ; R11.1 64.812,49.124 ; R12.1 64.292,52.324 64.812,51.804 64.812,49.124
  BOTTOM w0.2: v1(61.99,46.571) 61.99,45.547 61.851,45.408 61.851,44.493 62.003,44.341 v1(62.003,43.779)
UART6_RX_1: J1.34 J4.14 | length 28.9
  TOP w0.15: J1.34 44.51,50.659 45.131,50.038 46.265,50.038 v1(46.337,50.11)
  BOTTOM w0.15: J4.14 39.319,36.04 40.77,37.492 42.838,37.492 43.92,38.573 43.92,40.38 45.118,41.578 47.891,41.578 49.209,42.897 49.209,44.639 46.337,47.51 v1(46.337,50.11)
UART6_TX_1: J1.36 J4.15 | length 28.2
  TOP w0.15: v1(45.562,50.727) 46.012,50.727 46.162,50.877 46.962,50.877 47.05,50.965 J1.36
  BOTTOM w0.15: J4.15 39.293,38.58 40.017,37.856 42.783,37.856 43.625,38.698 43.625,40.623 44.985,41.983 47.903,41.983 48.932,43.012 48.932,44.335 45.562,47.705 v1(45.562,50.727)
USBFS_D_1_N: J1.10 J3.2 | length 111.9
  TOP w0.24: J1.10 13.121,52.73 12.98,52.871 12.98,55.827 16.079,58.926 33.583,58.926 33.589,58.932 51.711,58.932 52.004,58.639 v1(52.032,58.639)
  BOTTOM w0.24: v1(52.032,58.639) 52.06,58.639 52.353,58.932 54.157,58.932 64.044,49.045 64.044,11.358 60.807,8.121 59.932,8.121 57.914,6.102 57.914,5.26 57.164,4.51 56.536,4.51 56.395,4.651 56.395,4.93 55.765,5.56 J3.2
USBFS_D_1_P: J1.8 J3.1 | length 114
  TOP w0.24: J1.8 12.399,52.73 12.54,52.871 12.54,56.009 15.897,59.366 33.401,59.366 33.407,59.372 51.711,59.372 52.004,59.664 v1(52.032,59.664)
  BOTTOM w0.24: v1(52.032,59.664) 52.06,59.664 52.353,59.372 54.34,59.372 64.484,49.227 64.484,11.175 60.989,7.68 60.114,7.68 58.354,5.92 58.354,5.077 57.347,4.07 56.536,4.07 56.395,3.929 56.395,3.65 55.765,3.02 J3.1
VEXT: D1.A D2.2 J9.1 J9.2 | length 17.5
  TOP w1.3: D1.A@4.064,62.856 4.073,62.865 5.949,62.865 7.791,64.707 11.494,64.707 12.217,65.43 J9.1 J9.2
VIN: D1.C J1.2 J3.16 | length 90.8
  TOP w0.6: J1.2 3.937,52.797 3.937,56.388
  TOP w1.3: 3.937,56.388 D1.C@3.937,58.556 ; D1.C@4.106,58.598 6.11,58.598 v1@6.807,58.598 ; v1(14.869,62.561) 47.603,62.561 v1(48.395,61.769)
  PWR w1.3: v1(48.395,61.769) 48.061,62.103 44.309,62.103 40.673,58.467 40.673,53.287 42.053,51.907 47.235,51.907 51.502,47.64 51.502,38.68 51.602,38.58 J3.16
  BOTTOM w1.3: v1@6.11,58.59 v1(6.814,58.59) 10.363,58.59 14.334,62.561 v1(14.869,62.561) 15.665,62.561 v1(15.674,62.552)
  other v1: 6.01,58.598 47.837,62.32
pads on no net: Fiducial_1.1 Fiducial_2.1 Fiducial_3.1 J2.1 J2.2 J2.3 J2.7 J2.8 J2.9 J2.13 J2.14 J2.15 J2.NC J2.SH1 J3.0 J4.0 J4.20 J4.29 J4.30 J6.6 J6.7 J6.8 J6.9

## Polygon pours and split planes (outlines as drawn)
+3V3 on PWR "+3V3_L03_P005" (solid, remove dead copper, pour order 5): 0,0 65.968,0 65.968,71.798 65.969,71.8 0,71.8
GND on PWR "GND_L03_P004" (solid, remove dead copper, pour order 4): 0,27.333 17.851,27.333 19.198,28.68 26.79,28.68 29.194,26.276 29.194,0 0,0
GND on GND "GND_L02_P001" (solid, remove dead copper, pour order 1): 0,0 65.968,0 65.968,71.798 65.969,71.8 0,71.8
GND on BOTTOM "GND_L04_P003" (solid, remove dead copper, pour order 3): 0,0 65.968,0 65.968,71.798 65.969,71.8 0,71.8
GND on TOP "GND_L01_P000" (solid, remove dead copper, pour order 0): 0,0 65.968,0 65.968,71.798 65.969,71.8 0,71.8

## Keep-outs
Keep-Out Layer:
  circle w0.1: c4,3.9 r2.889
  circle w0.1: c62,3.9 r2.889
  circle w0.1: c62,67.9 r2.889
  circle w0.1: c4,67.9 r2.889

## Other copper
TOP:
  pour cut-out: 0,41.402 15.815,41.402 15.815,27.347 0,27.347
GND:
  pour cut-out: 0,41.402 15.815,41.402 15.815,27.347 0,27.347
PWR:
  pour cut-out: 0,41.402 15.815,41.402 15.815,27.347 0,27.347
BOTTOM:
  pour cut-out: 0,41.402 15.815,41.402 15.815,27.347 0,27.347

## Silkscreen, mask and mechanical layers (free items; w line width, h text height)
Route Tool Path:
  lines w2: -1,8.03 -1,0.792 ccw(c0.792,0.792) 0.792,-1 ; -1,12.031 -1,33.9 ; -1,37.9 -1,59.77 ; -1,63.77 -1,71.008 ; 67,0.788 cw(c65.208,0.792) 65.208,-1 0.792,-1 ; 67,0.792 67,8.03 ; 67,12.031 67,33.9 ; 67,37.9 67,59.77 ; 67,63.77 67,71.008 ; -1,71.008 cw(c0.792,71.008) -1,71.012 ; -1,71.008 cw(c0,71.008) -1,71.012 ; -1,71.012 cw(c0.792,71.008) 0.788,72.8 ; 0.788,72.8 cw(c0.792,71.8) 0.792,72.8 ; 0.788,72.8 cw(c0.792,71.008) 0.792,72.8 ; 0.792,-1 0.792,-1 ; 0.792,72.8 65.212,72.8 cw(c65.208,71.008) 67,71.012 ; 67,71.008 ccw(c65.208,71.008) 67,71.012 ; 67,71.008 ccw(c66,71.008) 67,71.012 ; 64.208,72.8 cw(c64.208,71.008) 64.212,72.8 ccw(c64.208,71.8) 64.208,72.8
Board:
  lines w0.1: 66,0.792 cw(c65.208,0.792) 65.208,0 0.792,0 cw(c0.792,0.792) 0,0.792 0,71.008 cw(c0.792,71.008) 0.792,71.8 65.208,71.8 cw(c65.208,71.008) 66,71.008 ; 66,0.792 66,0.792 ; 66,0.792 66,71.008 ; 66,71.008 66,71.008
POGO_NORI:
  drawing of 200 lines, arcs and shapes, not listed
UNOR4:
  circle w0.013: c27.94,-67.352 r0.425
  circle w0.013: c30.48,-67.352 r0.425
  circle w0.013: c33.02,-67.352 r0.425
  circle w0.013: c35.56,-67.352 r0.425
  circle w0.013: c38.1,-67.352 r0.425
  circle w0.013: c40.64,-67.352 r0.425
  circle w0.013: c43.18,-67.352 r0.425
  circle w0.013: c45.72,-67.352 r0.425
  circle w0.013: c50.8,-67.352 r0.425
  circle w0.013: c53.34,-67.352 r0.425
  circle w0.013: c55.88,-67.352 r0.425
  circle w0.013: c58.42,-67.352 r0.425
  circle w0.013: c60.96,-67.352 r0.425
  circle w0.013: c63.5,-67.352 r0.425
  circle w0.013: c63.5,-19.092 r0.425
  circle w0.013: c60.96,-19.092 r0.425
  circle w0.013: c58.42,-19.092 r0.425
  circle w0.013: c55.88,-19.092 r0.425
  circle w0.013: c53.34,-19.092 r0.425
  circle w0.013: c50.8,-19.092 r0.425
  circle w0.013: c48.26,-19.092 r0.425
  circle w0.013: c45.72,-19.092 r0.425
  circle w0.013: c41.656,-19.092 r0.425
  circle w0.013: c39.116,-19.092 r0.425
  circle w0.013: c36.576,-19.092 r0.425
  circle w0.013: c34.036,-19.092 r0.425
  circle w0.013: c31.496,-19.092 r0.425
  circle w0.013: c28.956,-19.092 r0.425
  circle w0.013: c26.416,-19.092 r0.425
  circle w0.013: c23.876,-19.092 r0.425
  circle w0.013: c21.336,-19.092 r0.425
  circle w0.013: c18.796,-19.092 r0.425
  circle w0.013: c22.86,-67.352 r0.425
  circle w0.013: c20.32,-67.352 r0.425
  circle w0.013: c17.78,-67.352 r0.425
  lines w0.05: 3.03,-32.026 3.537,-32.026 ; 3.538,-32.534 3.538,-32.026 ; 3.537,-31.518 3.537,-32.026 ; 5.44,-61.836 5.69,-61.586 ; 5.44,-61.336 5.69,-61.586 ; 5.94,-61.836 5.69,-61.586 ; 5.94,-61.336 5.69,-61.586 ; 8.49,-66.786 8.74,-66.536 ; 8.49,-66.286 8.74,-66.536 ; 8.99,-66.786 8.74,-66.536 ; 8.99,-66.286 8.74,-66.536 ; 11.64,-61.836 11.89,-61.586 ; 11.64,-61.336 11.89,-61.586 ; 12.14,-61.836 11.89,-61.586 ; 12.14,-61.336 11.89,-61.586 ; 3.538,-32.026 4.045,-32.026 ; 4.045,-32.026 4.045,-32.026 ; -1.96,-66.436 12.44,-66.436 12.44,-57.036 -1.96,-57.036 -1.96,-66.436 ; -0.86,-36.786 -0.86,-27.236 5.94,-27.236 5.94,-28.186 5.94,-36.786 3.19,-36.786 -0.86,-36.786 ; 5.19,-62.486 ccw(c5.69,-62.486) 5.69,-62.986 ccw(c5.69,-62.486) 6.19,-62.486 6.19,-61.586 6.19,-60.686 ccw(c5.69,-60.686) 5.69,-60.186 ccw(c5.69,-60.686) 5.19,-60.686 5.19,-61.586 5.19,-62.486 ; 7.34,-66.536 cw(c7.84,-66.536) 7.84,-66.036 8.74,-66.036 9.64,-66.036 cw(c9.64,-66.536) 10.14,-66.536 cw(c9.64,-66.536) 9.64,-67.036 8.74,-67.036 7.84,-67.036 cw(c7.84,-66.536) 7.34,-66.536 ; 11.39,-62.486 ccw(c11.89,-62.486) 11.89,-62.986 ccw(c11.89,-62.486) 12.39,-62.486 12.39,-61.586 12.39,-60.686 ccw(c11.89,-60.686) 11.89,-60.186 ccw(c11.89,-60.686) 11.39,-60.686 11.39,-61.586 11.39,-62.486
  text "USBC" at 2.621,-30.973 h0.5
  text "DC JACK" at 7.024,-61.856 h0.5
